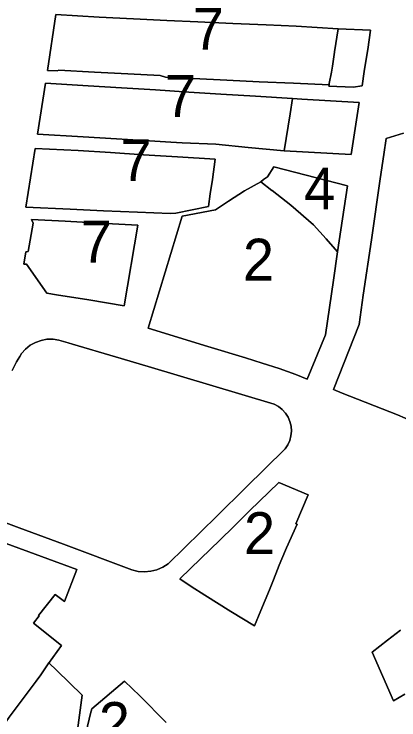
# Model space of a CAD drawing. Extents: x 598968 to 613553, y 4409678 to 4430833.
# Drawn here: x 607367.7 to 607478.1, y 4416375.4 to 4416577.8 of the extents above; entities that cross this region are included whole.
import ezdxf

# ---------------------------------------------------------------- set-up
doc = ezdxf.new("R2010")
doc.units = 0
for name, color, linetype in [('1', 7, 'Continuous'), ('ZONA 2. CARRERS DE CASES. Cases de trast', 7, 'Continuous'), ('ZONA 4. CASES UNIFAMILIRAS AÏLLADES EN PARCEL.LES', 7, 'Continuous'), ('ZONA 7. CONJUNTS AMB ORDENACIONS ESPECÍFIQUES', 7, 'Continuous')]:
    doc.layers.add(name, color=color, linetype=linetype)

msp = doc.modelspace()

# ---------------------------------------------------------------- linework, layer by layer
at = {"layer": '1'}
for points in [[(607377.3498, 4416561.5639), (607379.7497, 4416577.6138), (607392.1896, 4416576.864), (607401.9995, 4416576.4142), (607411.5693, 4416575.9643), (607420.4592, 4416575.5545), (607430.4691, 4416575.0847), (607440.029, 4416574.6749), (607448.6989, 4416574.285), (607460.6889, 4416573.5452), (607469.9688, 4416573.1254), (607469.2088, 4416567.6054), (607468.5788, 4416563.7155), (607468.2111, 4416561.3458), (607467.5718, 4416557.2249), (607464.9889, 4416556.8155), (607458.0589, 4416557.1154), (607458.1185, 4416557.452), (607458.1225, 4416557.4748), (607458.1089, 4416557.4754), (607447.879, 4416557.9252), (607438.0591, 4416558.365), (607428.7592, 4416558.8348), (607419.1293, 4416559.3047), (607411.1894, 4416559.7045), (607409.6194, 4416560.1445), (607400.3895, 4416560.6043), (607390.7996, 4416561.1142), (607380.5697, 4416561.684), (607380.1098, 4416561.454)], [(607458.1225, 4416557.4748), (607458.1185, 4416557.452), (607458.0589, 4416557.1154), (607464.9889, 4416556.8155), (607467.5718, 4416557.2249), (607468.2111, 4416561.3458), (607468.5788, 4416563.7155), (607469.2088, 4416567.6054), (607469.9688, 4416573.1254), (607460.6889, 4416573.5452), (607459.694, 4416566.9398), (607459.6924, 4416566.929), (607459.6786, 4416566.838), (607459.6777, 4416566.8321), (607459.0702, 4416562.8237), (607458.7691, 4416561.1236), (607458.1832, 4416557.8173)], [(607379.8498, 4416557.774), (607388.9597, 4416557.2342), (607398.5296, 4416556.6243), (607408.2895, 4416556.0045), (607417.8393, 4416555.4047), (607427.0392, 4416554.8149), (607437.0091, 4416554.205), (607447.609, 4416553.5652), (607450.3203, 4416553.3963), (607466.7137, 4416552.3745), (607464.4512, 4416537.5372), (607445.2499, 4416538.5071), (607445.2591, 4416538.5654), (607434.8592, 4416539.5452), (607425.6293, 4416540.415), (607415.9294, 4416540.8548), (607412.6895, 4416541.0048), (607406.5895, 4416541.3747), (607397.0996, 4416541.9545), (607387.5497, 4416542.5343), (607374.4199, 4416543.3241), (607376.7298, 4416557.964)], [(607445.2591, 4416538.5654), (607445.2499, 4416538.5071), (607464.4512, 4416537.5372), (607466.7137, 4416552.3745), (607450.3203, 4416553.3963), (607447.609, 4416553.5652), (607446.9119, 4416549.1156)], [(607386.1098, 4416538.6143), (607395.3697, 4416538.0445), (607404.8896, 4416537.4447), (607414.6494, 4416536.8449), (607425.419, 4416536.1725), (607425.4388, 4416536.1713), (607424.6394, 4416530.3351), (607423.9994, 4416526.2451), (607423.4794, 4416522.5452), (607414.1195, 4416520.685), (607412.5295, 4416520.535), (607403.1796, 4416520.9348), (607393.4197, 4416521.3447), (607383.8599, 4416521.8045), (607371.11, 4416522.4143), (607373.7599, 4416539.1741)], [(607448.6193, 4416474.3961), (607443.7464, 4416476.153), (607438.9594, 4416477.6859), (607434.1513, 4416479.1466), (607423.3133, 4416482.4705), (607406.2408, 4416487.6949), (607415.9795, 4416519.7751), (607425.4994, 4416521.6152), (607429.2501, 4416524.0901), (607433.8087, 4416527.0954), (607438.4992, 4416529.6654), (607439.2592, 4416530.3454), (607440.4492, 4416531.1354), (607442.2591, 4416533.9454), (607463.3853, 4416528.5096), (607460.5523, 4416509.5618), (607459.3588, 4416501.4284), (607457.0591, 4416485.7561), (607451.8592, 4416473.0361)], [(607382.3899, 4416518.3645), (607392.2998, 4416517.8247), (607403.1996, 4416517.2349), (607399.2798, 4416494.135), (607389.1499, 4416495.7848), (607379.87, 4416497.2947), (607377.12, 4416497.7447), (607371.3201, 4416506.0145), (607370.5101, 4416506.0344), (607371.12, 4416509.5444), (607371.79, 4416509.6744), (607373.25, 4416517.8444), (607372.77, 4416518.8843)], [(607421.3198, 4416421.6562), (607426.7397, 4416426.9462), (607430.7496, 4416430.8363), (607435.2896, 4416435.2763), (607443.7094, 4416443.4663), (607452.0726, 4416439.9086), (607448.6194, 4416431.6366), (607448.9094, 4416431.5166), (607445.8695, 4416424.6766), (607444.5795, 4416421.5866), (607443.8095, 4416419.7266), (607443.2895, 4416418.4966), (607442.1796, 4416415.5566), (607440.9796, 4416412.6567), (607438.4896, 4416406.7067), (607436.6897, 4416402.3867), (607429.9297, 4416406.4165), (607422.4298, 4416411.1863), (607418.5614, 4416413.6622), (607415.3299, 4416415.8362)]]:
    msp.add_lwpolyline(points, close=True, dxfattribs=at)
for points in [[(607488.779, 4416458.087), (607477.7191, 4416462.8967), (607461.8266, 4416469.1068), (607459.361, 4416470.1416), (607466.7032, 4416488.7458), (607467.9276, 4416497.1235), (607470.247, 4416512.9937), (607472.8034, 4416530.4856), (607473.8256, 4416537.4796), (607474.5055, 4416542.1323), (607479.441, 4416543.5718)], [(607367.1502, 4416475.5146), (607368.3879, 4416478.0158), (607369.3413, 4416479.5583), (607369.8552, 4416480.3896), (607370.995, 4416481.6896), (607372.3376, 4416482.7792), (607373.8444, 4416483.6272), (607375.4725, 4416484.2092), (607377.1754, 4416484.5088), (607378.9042, 4416484.5174), (607380.61, 4416484.2348), (607383.281, 4416483.4569), (607384.5382, 4416483.0909), (607396.8349, 4416479.5101), (607406.1756, 4416476.7139), (607442.3794, 4416465.8761), (607443.5861, 4416465.2106), (607444.6666, 4416464.3554), (607445.5915, 4416463.3339), (607446.3354, 4416462.174), (607446.8781, 4416460.9073), (607447.2047, 4416459.5685), (607447.3063, 4416458.1942), (607447.1801, 4416456.822), (607446.8295, 4416455.4894), (607446.2641, 4416454.2327), (607445.4994, 4416453.0863), (607434.0996, 4416441.8962), (607425.965, 4416433.9228), (607411.9199, 4416420.1561), (607410.3925, 4416419.1641), (607408.8758, 4416418.499), (607408.7246, 4416418.4327), (607406.9604, 4416417.9811), (607405.1462, 4416417.8213), (607403.3301, 4416417.9573), (607402.9826, 4416418.0414), (607401.56, 4416418.3859), (607381.8781, 4416425.7157), (607369.2249, 4416430.4278), (607369.2138, 4416430.4319), (607356.3705, 4416435.2149)], [(607356.3705, 4416435.2149), (607369.2138, 4416430.4319), (607369.2249, 4416430.4278), (607381.8781, 4416425.7157), (607401.56, 4416418.3859), (607402.9826, 4416418.0414), (607403.3301, 4416417.9573), (607405.1462, 4416417.8213), (607406.9604, 4416417.9811), (607408.7246, 4416418.4327), (607408.8758, 4416418.499), (607410.3925, 4416419.1641), (607411.9199, 4416420.1561), (607425.965, 4416433.9228), (607434.0996, 4416441.8962), (607445.4994, 4416453.0863), (607446.2641, 4416454.2327), (607446.8295, 4416455.4894), (607447.1801, 4416456.822), (607447.3063, 4416458.1942), (607447.2047, 4416459.5685), (607446.8781, 4416460.9073), (607446.3354, 4416462.174), (607445.5915, 4416463.3339), (607444.6666, 4416464.3554), (607443.5861, 4416465.2106), (607442.3794, 4416465.8761), (607406.1756, 4416476.7139), (607396.8349, 4416479.5101), (607384.5382, 4416483.0909), (607383.281, 4416483.4569), (607380.61, 4416484.2348), (607378.9042, 4416484.5174), (607377.1754, 4416484.5088), (607375.4725, 4416484.2092), (607373.8444, 4416483.6272), (607372.3376, 4416482.7792), (607370.995, 4416481.6896), (607369.8552, 4416480.3896), (607369.3413, 4416479.5583), (607368.3879, 4416478.0158), (607367.1502, 4416475.5146)], [(607325.5011, 4416366.6452), (607330.411, 4416379.1751), (607331.631, 4416382.0451), (607336.2109, 4416393.685), (607341.62, 4416407.2132), (607349.5406, 4416427.0349), (607355.2105, 4416429.725), (607385.6902, 4416418.5156), (607382.1903, 4416409.3257), (607379.5603, 4416411.3356), (607374.7104, 4416405.2856), (607374.9704, 4416405.1856), (607373.2804, 4416403.1556), (607381.3603, 4416396.6858), (607377.5854, 4416391.5608), (607377.7055, 4416391.711), (607379.9804, 4416389.5359), (607387.2703, 4416382.4361), (607385.9204, 4416372.4362)], [(607479.8793, 4416382.7677), (607476.5894, 4416380.8176), (607470.4494, 4416394.8074), (607474.9093, 4416398.2374), (607478.6193, 4416401.0974)], [(607388.4203, 4416371.9962), (607389.6603, 4416377.2362), (607390.0403, 4416378.5262), (607399.3937, 4416386.5224), (607403.8501, 4416382.2764), (607411.3501, 4416374.5866)]]:
    msp.add_lwpolyline(points, dxfattribs=at)
at = {"layer": 'ZONA 2. CARRERS DE CASES. Cases de trast'}
for points in [[(607479.441, 4416543.5718), (607474.5055, 4416542.1323), (607473.8256, 4416537.4796), (607472.8034, 4416530.4856), (607470.247, 4416512.9937), (607467.9276, 4416497.1235), (607466.7032, 4416488.7458), (607459.361, 4416470.1416), (607461.8266, 4416469.1068), (607477.7191, 4416462.8967), (607488.779, 4416458.087)], [(607365.4306, 4416374.8958), (607366.3606, 4416376.1358), (607374.0904, 4416386.4658), (607375.4404, 4416388.2658), (607375.4549, 4416388.2879), (607377.322, 4416391.1277), (607377.7055, 4416391.711), (607377.5854, 4416391.5608), (607381.3603, 4416396.6858), (607373.2804, 4416403.1556), (607374.9704, 4416405.1856), (607374.7104, 4416405.2856), (607379.5603, 4416411.3356), (607382.1903, 4416409.3257), (607385.6902, 4416418.5156), (607355.2105, 4416429.725), (607349.5406, 4416427.0349), (607341.62, 4416407.2132), (607336.2109, 4416393.685), (607331.631, 4416382.0451), (607330.411, 4416379.1751), (607325.5011, 4416366.6452)], [(607478.6193, 4416401.0974), (607474.9093, 4416398.2374), (607470.4494, 4416394.8074), (607476.5894, 4416380.8176), (607479.8793, 4416382.7677)], [(607385.9204, 4416372.4362), (607387.2703, 4416382.4361), (607379.9804, 4416389.5359), (607377.7055, 4416391.711), (607377.322, 4416391.1277), (607375.4549, 4416388.2879), (607375.4404, 4416388.2658), (607374.0904, 4416386.4658), (607366.3606, 4416376.1358), (607365.4306, 4416374.8958)], [(607411.3501, 4416374.5866), (607403.8501, 4416382.2764), (607399.3937, 4416386.5224), (607390.0403, 4416378.5262), (607389.6603, 4416377.2362), (607388.4203, 4416371.9962)]]:
    msp.add_lwpolyline(points, dxfattribs=at)
for points in [[(607460.5523, 4416509.5618), (607457.239, 4416513.3259), (607453.6191, 4416517.3058), (607447.1191, 4416523.0156), (607441.7362, 4416527.1664), (607441.6792, 4416527.2104), (607438.4992, 4416529.6654), (607433.8087, 4416527.0954), (607429.2501, 4416524.0901), (607425.4994, 4416521.6152), (607415.9795, 4416519.7751), (607406.2408, 4416487.6949), (607423.3133, 4416482.4705), (607434.1513, 4416479.1466), (607438.9594, 4416477.6859), (607443.7464, 4416476.153), (607448.6193, 4416474.3961), (607451.8592, 4416473.0361), (607457.0591, 4416485.7561), (607459.3588, 4416501.4284)], [(607438.4896, 4416406.7067), (607440.9796, 4416412.6567), (607442.1796, 4416415.5566), (607443.2895, 4416418.4966), (607443.8095, 4416419.7266), (607444.5795, 4416421.5866), (607445.8695, 4416424.6766), (607448.9094, 4416431.5166), (607448.6194, 4416431.6366), (607452.0726, 4416439.9086), (607443.7094, 4416443.4663), (607435.2896, 4416435.2763), (607430.7496, 4416430.8363), (607426.7397, 4416426.9462), (607421.3198, 4416421.6562), (607415.3299, 4416415.8362), (607418.5614, 4416413.6622), (607422.4298, 4416411.1863), (607429.9297, 4416406.4165), (607436.6897, 4416402.3867)]]:
    msp.add_lwpolyline(points, close=True, dxfattribs=at)
at = {"layer": 'ZONA 4. CASES UNIFAMILIRAS AÏLLADES EN PARCEL.LES'}
msp.add_lwpolyline([(607460.5523, 4416509.5618), (607463.3853, 4416528.5096), (607442.2591, 4416533.9454), (607440.4492, 4416531.1354), (607439.2592, 4416530.3454), (607438.4992, 4416529.6654), (607441.6792, 4416527.2104), (607441.7362, 4416527.1664), (607447.1191, 4416523.0156), (607453.6191, 4416517.3058), (607457.239, 4416513.3259)], close=True, dxfattribs=at)
at = {"layer": 'ZONA 7. CONJUNTS AMB ORDENACIONS ESPECÍFIQUES'}
for points in [[(607460.6889, 4416573.5452), (607448.6989, 4416574.285), (607440.029, 4416574.6749), (607430.4691, 4416575.0847), (607420.4592, 4416575.5545), (607411.5693, 4416575.9643), (607401.9995, 4416576.4142), (607392.1896, 4416576.864), (607379.7497, 4416577.6138), (607377.3498, 4416561.5639), (607380.1098, 4416561.454), (607380.5697, 4416561.684), (607390.7996, 4416561.1142), (607400.3895, 4416560.6043), (607409.6194, 4416560.1445), (607411.1894, 4416559.7045), (607419.1293, 4416559.3047), (607428.7592, 4416558.8348), (607438.0591, 4416558.365), (607447.879, 4416557.9252), (607458.1089, 4416557.4754), (607458.1225, 4416557.4748), (607458.1832, 4416557.8173), (607458.7691, 4416561.1236), (607459.0702, 4416562.8237), (607459.6777, 4416566.8321), (607459.6786, 4416566.838), (607459.6924, 4416566.929), (607459.694, 4416566.9398)], [(607447.609, 4416553.5652), (607437.0091, 4416554.205), (607427.0392, 4416554.8149), (607417.8393, 4416555.4047), (607408.2895, 4416556.0045), (607398.5296, 4416556.6243), (607388.9597, 4416557.2342), (607379.8498, 4416557.774), (607376.7298, 4416557.964), (607374.4199, 4416543.3241), (607387.5497, 4416542.5343), (607397.0996, 4416541.9545), (607406.5895, 4416541.3747), (607412.6895, 4416541.0048), (607415.9294, 4416540.8548), (607425.6293, 4416540.415), (607434.8592, 4416539.5452), (607445.2591, 4416538.5654), (607446.9119, 4416549.1156)], [(607414.1195, 4416520.685), (607423.4794, 4416522.5452), (607423.9994, 4416526.2451), (607424.6394, 4416530.3351), (607425.4388, 4416536.1713), (607425.419, 4416536.1725), (607414.6494, 4416536.8449), (607404.8896, 4416537.4447), (607395.3697, 4416538.0445), (607386.1098, 4416538.6143), (607373.7599, 4416539.1741), (607371.11, 4416522.4143), (607383.8599, 4416521.8045), (607393.4197, 4416521.3447), (607403.1796, 4416520.9348), (607412.5295, 4416520.535)], [(607403.1996, 4416517.2349), (607392.2998, 4416517.8247), (607382.3899, 4416518.3645), (607372.77, 4416518.8843), (607373.25, 4416517.8444), (607371.79, 4416509.6744), (607371.12, 4416509.5444), (607370.5101, 4416506.0344), (607371.3201, 4416506.0145), (607377.12, 4416497.7447), (607379.87, 4416497.2947), (607389.1499, 4416495.7848), (607399.2798, 4416494.135)]]:
    msp.add_lwpolyline(points, close=True, dxfattribs=at)

# ---------------------------------------------------------------- texts
at = {"layer": 'ZONA 2. CARRERS DE CASES. Cases de trast'}
for p in [(607433.3965, 4416501.3508), (607433.7012, 4416422.9265), (607392.0584, 4416368.4814)]:
    msp.add_text('2', height=12, dxfattribs=at).set_placement(p)
at = {"layer": 'ZONA 4. CASES UNIFAMILIRAS AÏLLADES EN PARCEL.LES'}
msp.add_text('4', height=12, dxfattribs=at).set_placement((607450.9423, 4416521.7536))
at = {"layer": 'ZONA 7. CONJUNTS AMB ORDENACIONS ESPECÍFIQUES'}
for p in [(607419.0194, 4416567.5443), (607411.0145, 4416548.2647), (607398.2744, 4416529.8546), (607386.8548, 4416506.5096)]:
    msp.add_text('7', height=12, dxfattribs=at).set_placement(p)

doc.saveas('drawing.dxf')
